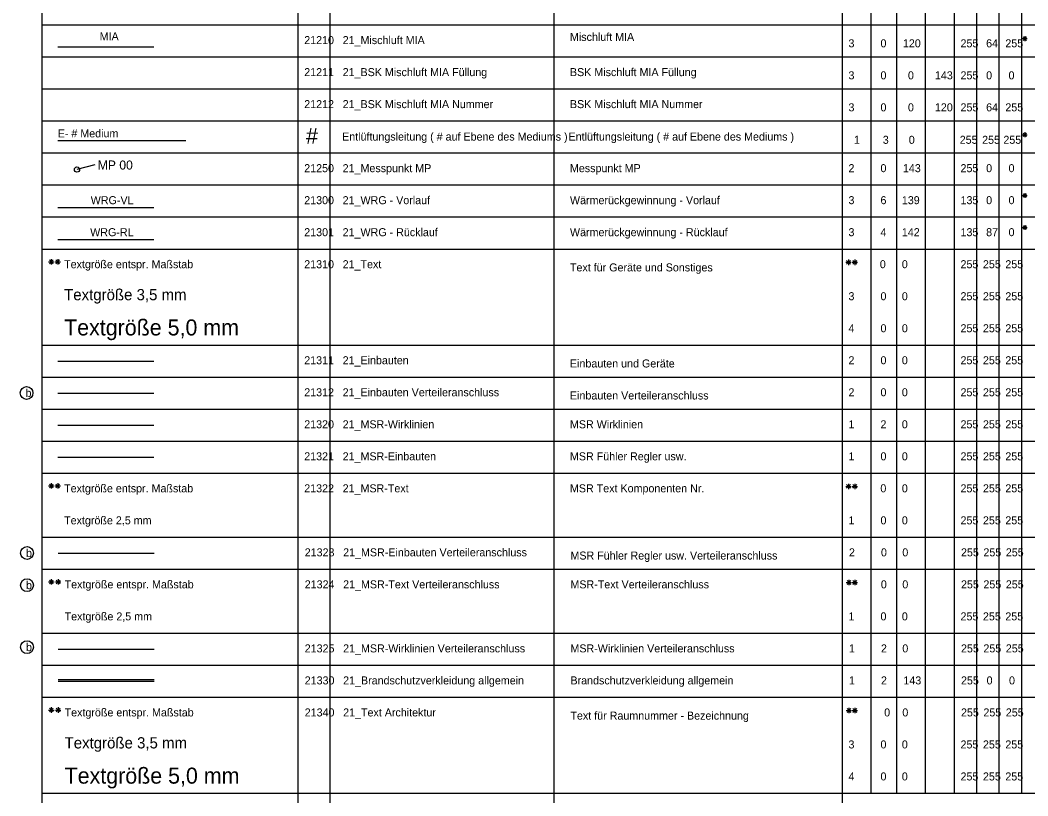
# Model space of a CAD drawing. Extents: x -26 to 55, y -9 to 161.
# Drawn here: x -0.67 to 30.8, y 27.92 to 52.15 of the extents above; entities that cross this region are included whole.
import ezdxf

# ---------------------------------------------------------------- set-up
doc = ezdxf.new("R2010")
doc.units = 0
for name, color, linetype in [('21_Brandschutzverkleidung allgemein', 7, 'Continuous'), ('21_Einbauten', 7, 'Continuous'), ('21_Einbauten Verteileranschluss', 7, 'Continuous'), ('21_Messpunkt MP', 7, 'Continuous'), ('21_Mischluft MIA', 7, 'Continuous'), ('21_MSR-Einbauten', 7, 'Continuous'), ('21_MSR-Einbauten Verteileranschluss', 7, 'Continuous'), ('21_MSR-Text', 7, 'Continuous'), ('21_MSR-Text Verteileranschluss', 7, 'Continuous'), ('21_MSR-Wirklinien', 7, 'Continuous'), ('21_MSR-Wirklinien Verteileranschluss', 7, 'Continuous'), ('21_Text', 7, 'Continuous'), ('21_Text Architektur', 7, 'Continuous'), ('21_WRG - Rücklauf', 7, 'Continuous'), ('21_WRG - Vorlauf', 7, 'Continuous'), ('21_z_freie_Ebene_01', 7, 'Continuous'), ('90_Alter Index', 7, 'Continuous'), ('Default', 7, 'Continuous')]:
    doc.layers.add(name, color=color, linetype=linetype)

msp = doc.modelspace()

# ---------------------------------------------------------------- linework, layer by layer
at = {"layer": '21_Brandschutzverkleidung allgemein'}
for p, q in [((0.515, 31.55), (3.515, 31.55)), ((0.515, 31.5), (3.515, 31.5))]:
    msp.add_line(p, q, dxfattribs=at)
at = {"layer": '21_Einbauten'}
msp.add_line((0.5, 41.5), (3.5, 41.5), dxfattribs=at)
at = {"layer": '21_Einbauten Verteileranschluss'}
msp.add_line((0.5, 40.5), (3.5, 40.5), dxfattribs=at)
at = {"layer": '21_Messpunkt MP'}
msp.add_line((1.655, 47.629), (1.102, 47.481), dxfattribs=at)
msp.add_circle((1.102, 47.481), 0.081, dxfattribs=at)
at = {"layer": '21_Mischluft MIA'}
msp.add_line((0.5, 51.318), (3.5, 51.318), dxfattribs=at)
at = {"layer": '21_MSR-Einbauten'}
msp.add_line((0.5, 38.5), (3.5, 38.5), dxfattribs=at)
at = {"layer": '21_MSR-Einbauten Verteileranschluss'}
msp.add_line((0.515, 35.5), (3.515, 35.5), dxfattribs=at)
at = {"layer": '21_MSR-Wirklinien'}
msp.add_line((0.5, 39.5), (3.5, 39.5), dxfattribs=at)
at = {"layer": '21_MSR-Wirklinien Verteileranschluss'}
msp.add_line((0.515, 32.5), (3.515, 32.5), dxfattribs=at)
at = {"layer": '21_WRG - Rücklauf'}
msp.add_line((0.5, 45.3), (3.5, 45.3), dxfattribs=at)
at = {"layer": '21_WRG - Vorlauf'}
msp.add_line((0.5, 46.3), (3.5, 46.3), dxfattribs=at)
at = {"layer": '21_z_freie_Ebene_01'}
msp.add_line((0.5, 48.386), (4.5, 48.386), dxfattribs=at)
at = {"layer": '90_Alter Index'}
for centre in [(-0.473, 40.503), (-0.458, 35.503), (-0.458, 34.5), (-0.458, 32.564)]:
    msp.add_circle(centre, 0.2, dxfattribs=at)
at = {"layer": 'Default'}
for p, q in [((0, 147), (0, 0)), ((8, 147), (8, 0)), ((9, 147), (9, 0)), ((16, 147), (16, 0)), ((25, 147), (25, 0)), ((25.9, 146.3), (25.9, 28)), ((26.7, 146.3), (26.7, 28)), ((27.6, 146.3), (27.6, 28)), ((28.5, 146.3), (28.5, 28)), ((30.6, 146.3), (30.6, 28)), ((29.2, 145.5), (29.2, 28)), ((29.9, 145.5), (29.9, 28)), ((0, 52), (33.6, 52)), ((30.657, 51.623), (30.763, 51.517)), ((30.763, 51.623), (30.657, 51.517)), ((30.71, 51.646), (30.71, 51.494)), ((30.634, 51.57), (30.786, 51.57)), ((0, 51), (33.6, 51)), ((0, 50), (33.6, 50)), ((0, 49), (33.6, 49)), ((30.634, 48.57), (30.786, 48.57)), ((30.657, 48.623), (30.763, 48.517)), ((30.763, 48.623), (30.657, 48.517)), ((30.71, 48.646), (30.71, 48.494)), ((0, 48), (33.6, 48)), ((0, 47), (33.6, 47)), ((30.634, 46.67), (30.786, 46.67)), ((30.657, 46.723), (30.763, 46.617)), ((30.763, 46.723), (30.657, 46.617)), ((30.71, 46.746), (30.71, 46.594)), ((0, 46), (33.6, 46)), ((30.634, 45.67), (30.786, 45.67)), ((30.657, 45.723), (30.763, 45.617)), ((30.763, 45.723), (30.657, 45.617)), ((30.71, 45.746), (30.71, 45.594)), ((0, 45), (33.6, 45)), ((0.216, 44.6), (0.384, 44.6)), ((0.241, 44.659), (0.359, 44.541)), ((0.359, 44.659), (0.241, 44.541)), ((0.3, 44.684), (0.3, 44.516)), ((0.416, 44.6), (0.584, 44.6)), ((0.441, 44.659), (0.559, 44.541)), ((0.559, 44.659), (0.441, 44.541)), ((0.5, 44.684), (0.5, 44.516)), ((25.116, 44.584), (25.284, 44.584)), ((25.141, 44.643), (25.259, 44.525)), ((25.259, 44.643), (25.141, 44.525)), ((25.2, 44.668), (25.2, 44.5)), ((25.316, 44.584), (25.484, 44.584)), ((25.341, 44.643), (25.459, 44.525)), ((25.459, 44.643), (25.341, 44.525)), ((25.4, 44.668), (25.4, 44.5)), ((0, 42), (33.6, 42)), ((0, 41), (33.6, 41)), ((0, 40), (33.6, 40)), ((0, 39), (33.6, 39)), ((0, 38), (33.6, 38)), ((0.216, 37.6), (0.384, 37.6)), ((0.241, 37.659), (0.359, 37.541)), ((0.359, 37.659), (0.241, 37.541)), ((0.3, 37.684), (0.3, 37.516)), ((0.416, 37.6), (0.584, 37.6)), ((0.441, 37.659), (0.559, 37.541)), ((0.559, 37.659), (0.441, 37.541)), ((0.5, 37.684), (0.5, 37.516)), ((25.116, 37.584), (25.284, 37.584)), ((25.141, 37.643), (25.259, 37.525)), ((25.259, 37.643), (25.141, 37.525)), ((25.2, 37.668), (25.2, 37.5)), ((25.316, 37.584), (25.484, 37.584)), ((25.341, 37.643), (25.459, 37.525)), ((25.459, 37.643), (25.341, 37.525)), ((25.4, 37.668), (25.4, 37.5)), ((0.015, 36), (33.615, 36)), ((0.031, 35), (33.615, 35)), ((0.241, 34.659), (0.359, 34.541)), ((0.359, 34.659), (0.241, 34.541)), ((0.3, 34.684), (0.3, 34.516)), ((0.456, 34.659), (0.575, 34.541)), ((0.575, 34.659), (0.456, 34.541)), ((0.515, 34.684), (0.515, 34.516)), ((25.156, 34.643), (25.275, 34.525)), ((25.275, 34.643), (25.156, 34.525)), ((25.215, 34.668), (25.215, 34.5)), ((25.341, 34.643), (25.459, 34.525)), ((25.459, 34.643), (25.341, 34.525)), ((25.4, 34.668), (25.4, 34.5)), ((0.216, 34.6), (0.384, 34.6)), ((0.432, 34.6), (0.599, 34.6)), ((25.132, 34.584), (25.299, 34.584)), ((25.316, 34.584), (25.484, 34.584)), ((0.015, 33), (33.615, 33)), ((0.015, 32), (33.615, 32)), ((0.015, 31), (33.615, 31)), ((0.216, 30.6), (0.384, 30.6)), ((0.241, 30.659), (0.359, 30.541)), ((0.359, 30.659), (0.241, 30.541)), ((0.3, 30.684), (0.3, 30.516)), ((0.432, 30.6), (0.599, 30.6)), ((0.456, 30.659), (0.575, 30.541)), ((0.575, 30.659), (0.456, 30.541)), ((0.515, 30.684), (0.515, 30.516)), ((25.132, 30.584), (25.299, 30.584)), ((25.156, 30.643), (25.275, 30.525)), ((25.275, 30.643), (25.156, 30.525)), ((25.215, 30.668), (25.215, 30.5)), ((25.316, 30.584), (25.484, 30.584)), ((25.341, 30.643), (25.459, 30.525)), ((25.459, 30.643), (25.341, 30.525)), ((25.4, 30.668), (25.4, 30.5)), ((0.015, 28), (33.615, 28))]:
    msp.add_line(p, q, dxfattribs=at)

# ---------------------------------------------------------------- texts
at = {"layer": '21_Messpunkt MP'}
msp.add_text('MP 00', height=0.2835, dxfattribs=at).set_placement((1.75, 47.481))
at = {"layer": '21_Mischluft MIA'}
msp.add_text('MIA', height=0.25, dxfattribs=at).set_placement((1.81, 51.518))
at = {"layer": '21_MSR-Text'}
msp.add_text('Textgröße 2,5 mm', height=0.25, dxfattribs=at).set_placement((0.7, 36.4))
at = {"layer": '21_MSR-Text Verteileranschluss'}
msp.add_text('Textgröße 2,5 mm', height=0.25, dxfattribs=at).set_placement((0.715, 33.4))
at = {"layer": '21_Text'}
for s, height, p in [('Textgröße 3,5 mm', 0.35, (0.7, 43.4)), ('Textgröße 5,0 mm', 0.5, (0.7, 42.3))]:
    msp.add_text(s, height=height, dxfattribs=at).set_placement(p)
at = {"layer": '21_Text Architektur'}
for s, height, p in [('Textgröße 3,5 mm', 0.35, (0.715, 29.4)), ('Textgröße 5,0 mm', 0.5, (0.715, 28.3))]:
    msp.add_text(s, height=height, dxfattribs=at).set_placement(p)
at = {"layer": '21_WRG - Rücklauf'}
msp.add_text('WRG-RL', height=0.25, dxfattribs=at).set_placement((1.514, 45.4))
at = {"layer": '21_WRG - Vorlauf'}
msp.add_text('WRG-VL', height=0.25, dxfattribs=at).set_placement((1.531, 46.4))
at = {"layer": '21_z_freie_Ebene_01'}
msp.add_text('E- # Medium', height=0.25, dxfattribs=at).set_placement((0.5, 48.486))
at = {"layer": '90_Alter Index'}
for p in [(-0.506, 40.378), (-0.49, 35.378), (-0.49, 34.375), (-0.49, 32.439)]:
    msp.add_text('b', height=0.25, dxfattribs=at).set_placement(p)
at = {"layer": 'Default'}
for s, height, p in [('21210', 0.25, (8.2, 51.4)), ('21_Mischluft MIA ', 0.25, (9.4, 51.4)), ('Mischluft MIA ', 0.25, (16.5, 51.5)), ('3', 0.25, (25.2, 51.3)), ('0', 0.25, (26.2, 51.3)), ('120', 0.25, (26.9, 51.3)), ('255', 0.25, (28.7, 51.3)), ('64', 0.25, (29.5, 51.3)), ('255', 0.25, (30.1, 51.3)), ('21211', 0.25, (8.2, 50.4)), ('21_BSK Mischluft MIA Füllung', 0.25, (9.4, 50.4)), ('BSK Mischluft MIA Füllung', 0.25, (16.5, 50.4)), ('3', 0.25, (25.2, 50.3)), ('0', 0.25, (26.2, 50.3)), ('0', 0.25, (27.058, 50.3)), ('143', 0.25, (27.9, 50.3)), ('255', 0.25, (28.7, 50.3)), ('0', 0.25, (29.5, 50.3)), ('0', 0.25, (30.2, 50.3)), ('21212', 0.25, (8.2, 49.4)), ('21_BSK Mischluft MIA Nummer', 0.25, (9.4, 49.4)), ('BSK Mischluft MIA Nummer', 0.25, (16.5, 49.4)), ('3', 0.25, (25.2, 49.3)), ('0', 0.25, (26.2, 49.3)), ('0', 0.25, (27.058, 49.3)), ('120', 0.25, (27.9, 49.3)), ('255', 0.25, (28.7, 49.3)), ('64', 0.25, (29.5, 49.3)), ('255', 0.25, (30.1, 49.3)), (' # ', 0.5, (8.071, 48.286)), (' Entlüftungsleitung ( # auf Ebene des Mediums )', 0.25, (9.29, 48.386)), (' Entlüftungsleitung ( # auf Ebene des Mediums )', 0.25, (16.364, 48.386)), ('1', 0.25, (25.371, 48.286)), ('3', 0.25, (26.271, 48.286)), ('0', 0.25, (27.084, 48.286)), ('255', 0.25, (28.675, 48.286)), ('255', 0.25, (29.375, 48.286)), ('255', 0.25, (30.039, 48.286)), ('21250', 0.25, (8.2, 47.4)), ('21_Messpunkt MP', 0.25, (9.4, 47.4)), ('Messpunkt MP', 0.25, (16.5, 47.4)), ('2', 0.25, (25.2, 47.4)), ('0 ', 0.25, (26.2, 47.4)), ('143', 0.25, (26.9, 47.4)), ('255', 0.25, (28.7, 47.4)), ('0', 0.25, (29.5, 47.4)), ('0', 0.25, (30.2, 47.4)), ('21300', 0.25, (8.2, 46.4)), ('21_WRG - Vorlauf', 0.25, (9.4, 46.4)), ('Wärmerückgewinnung - Vorlauf ', 0.25, (16.5, 46.4)), ('3', 0.25, (25.2, 46.4)), ('6', 0.25, (26.2, 46.4)), ('139', 0.25, (26.867, 46.4)), ('135', 0.25, (28.7, 46.4)), ('0', 0.25, (29.5, 46.4)), ('0', 0.25, (30.2, 46.4)), ('21301', 0.25, (8.2, 45.4)), ('21_WRG - Rücklauf', 0.25, (9.4, 45.4)), ('Wärmerückgewinnung - Rücklauf ', 0.25, (16.5, 45.4)), ('3', 0.25, (25.2, 45.4)), ('4', 0.25, (26.2, 45.4)), ('142', 0.25, (26.867, 45.4)), ('135', 0.25, (28.7, 45.4)), ('87', 0.25, (29.5, 45.4)), ('0', 0.25, (30.2, 45.4)), ('Textgröße entspr. Maßstab', 0.25, (0.7, 44.4)), ('21310', 0.25, (8.2, 44.4)), ('21_Text', 0.25, (9.4, 44.4)), ('Text für Geräte und Sonstiges', 0.25, (16.5, 44.3)), ('0', 0.25, (26.18, 44.4)), ('0', 0.25, (26.867, 44.4)), ('255', 0.25, (28.7, 44.4)), ('255', 0.25, (29.4, 44.4)), ('255', 0.25, (30.1, 44.4)), ('3', 0.25, (25.2, 43.4)), ('0', 0.25, (26.2, 43.4)), ('0', 0.25, (26.867, 43.4)), ('255', 0.25, (28.7, 43.4)), ('255', 0.25, (29.4, 43.4)), ('255', 0.25, (30.1, 43.4)), ('4', 0.25, (25.2, 42.4)), ('0', 0.25, (26.2, 42.4)), ('0', 0.25, (26.867, 42.4)), ('255', 0.25, (28.7, 42.4)), ('255', 0.25, (29.4, 42.4)), ('255', 0.25, (30.1, 42.4)), ('21311', 0.25, (8.2, 41.4)), ('21_Einbauten', 0.25, (9.4, 41.4)), ('Einbauten und Geräte', 0.25, (16.5, 41.3)), ('2', 0.25, (25.2, 41.4)), ('0', 0.25, (26.2, 41.4)), ('0', 0.25, (26.867, 41.4)), ('255', 0.25, (28.7, 41.4)), ('255', 0.25, (29.4, 41.4)), ('255', 0.25, (30.1, 41.4)), ('21312', 0.25, (8.2, 40.4)), ('21_Einbauten Verteileranschluss', 0.25, (9.4, 40.4)), ('2', 0.25, (25.2, 40.4)), ('0', 0.25, (26.2, 40.4)), ('0', 0.25, (26.867, 40.4)), ('255', 0.25, (28.7, 40.4)), ('255', 0.25, (29.4, 40.4)), ('255', 0.25, (30.1, 40.4)), ('Einbauten Verteileranschluss', 0.25, (16.5, 40.3)), ('21_MSR-Wirklinien', 0.25, (9.4, 39.4)), ('MSR Wirklinien', 0.25, (16.5, 39.4)), ('21320', 0.25, (8.2, 39.4)), ('1', 0.25, (25.2, 39.4)), ('2', 0.25, (26.2, 39.4)), ('0', 0.25, (26.867, 39.4)), ('255', 0.25, (28.7, 39.4)), ('255', 0.25, (29.4, 39.4)), ('255', 0.25, (30.1, 39.4)), ('21321', 0.25, (8.2, 38.4)), ('21_MSR-Einbauten', 0.25, (9.4, 38.4)), ('MSR Fühler Regler usw.', 0.25, (16.5, 38.4)), ('1', 0.25, (25.2, 38.4)), ('0', 0.25, (26.2, 38.4)), ('0', 0.25, (26.867, 38.4)), ('255', 0.25, (28.7, 38.4)), ('255', 0.25, (29.4, 38.4)), ('255', 0.25, (30.1, 38.4)), ('Textgröße entspr. Maßstab', 0.25, (0.7, 37.4)), ('21322', 0.25, (8.2, 37.4)), ('21_MSR-Text', 0.25, (9.4, 37.4)), ('MSR Text Komponenten Nr. ', 0.25, (16.5, 37.4)), ('0', 0.25, (26.196, 37.4)), ('0', 0.25, (26.867, 37.4)), ('255', 0.25, (28.7, 37.4)), ('255', 0.25, (29.4, 37.4)), ('255', 0.25, (30.1, 37.4)), ('1', 0.25, (25.2, 36.4)), ('0', 0.25, (26.2, 36.4)), ('0', 0.25, (26.867, 36.4)), ('255', 0.25, (28.7, 36.4)), ('255', 0.25, (29.4, 36.4)), ('255', 0.25, (30.1, 36.4)), ('21323', 0.25, (8.215, 35.4)), ('21_MSR-Einbauten Verteileranschluss', 0.25, (9.415, 35.4)), ('2', 0.25, (25.215, 35.4)), ('0', 0.25, (26.215, 35.4)), ('0', 0.25, (26.882, 35.4)), ('255', 0.25, (28.715, 35.4)), ('255', 0.25, (29.415, 35.4)), ('255', 0.25, (30.115, 35.4)), ('MSR Fühler Regler usw. Verteileranschluss', 0.25, (16.515, 35.3)), ('Textgröße entspr. Maßstab', 0.25, (0.715, 34.4)), ('21324', 0.25, (8.215, 34.4)), ('21_MSR-Text Verteileranschluss', 0.25, (9.415, 34.4)), ('MSR-Text Verteileranschluss', 0.25, (16.515, 34.4)), ('0', 0.25, (26.212, 34.4)), ('0', 0.25, (26.882, 34.4)), ('255', 0.25, (28.715, 34.4)), ('255', 0.25, (29.415, 34.4)), ('255', 0.25, (30.115, 34.4)), ('1', 0.25, (25.2, 33.4)), ('0', 0.25, (26.2, 33.4)), ('0', 0.25, (26.867, 33.4)), ('255', 0.25, (28.7, 33.4)), ('255', 0.25, (29.4, 33.4)), ('255', 0.25, (30.1, 33.4)), ('21325', 0.25, (8.215, 32.4)), ('21_MSR-Wirklinien Verteileranschluss', 0.25, (9.415, 32.4)), ('MSR-Wirklinien Verteileranschluss', 0.25, (16.515, 32.4)), ('1', 0.25, (25.215, 32.4)), ('2', 0.25, (26.215, 32.4)), ('0', 0.25, (26.882, 32.4)), ('255', 0.25, (28.715, 32.4)), ('255', 0.25, (29.415, 32.4)), ('255', 0.25, (30.115, 32.4)), ('21330', 0.25, (8.215, 31.4)), ('21_Brandschutzverkleidung allgemein', 0.25, (9.415, 31.4)), ('Brandschutzverkleidung allgemein', 0.25, (16.515, 31.4)), ('1', 0.25, (25.215, 31.4)), ('2', 0.25, (26.215, 31.4)), ('143', 0.25, (26.915, 31.4)), ('255', 0.25, (28.715, 31.4)), ('0', 0.25, (29.515, 31.4)), ('0', 0.25, (30.215, 31.4)), ('Textgröße entspr. Maßstab', 0.25, (0.715, 30.4)), ('21340', 0.25, (8.215, 30.4)), ('21_Text Architektur', 0.25, (9.415, 30.4)), ('Text für Raumnummer - Bezeichnung', 0.25, (16.515, 30.3)), ('0', 0.25, (26.315, 30.4)), ('0', 0.25, (26.882, 30.4)), ('255', 0.25, (28.715, 30.4)), ('255', 0.25, (29.415, 30.4)), ('255', 0.25, (30.115, 30.4)), ('3', 0.25, (25.2, 29.4)), ('0', 0.25, (26.2, 29.4)), ('0', 0.25, (26.867, 29.4)), ('255', 0.25, (28.7, 29.4)), ('255', 0.25, (29.4, 29.4)), ('255', 0.25, (30.1, 29.4)), ('4', 0.25, (25.2, 28.4)), ('0', 0.25, (26.2, 28.4)), ('0', 0.25, (26.867, 28.4)), ('255', 0.25, (28.7, 28.4)), ('255', 0.25, (29.4, 28.4)), ('255', 0.25, (30.1, 28.4))]:
    msp.add_text(s, height=height, dxfattribs=at).set_placement(p)

doc.saveas('drawing.dxf')
